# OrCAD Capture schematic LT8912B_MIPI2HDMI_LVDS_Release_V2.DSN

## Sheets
1 03.Revision History: company: Seabery Soluciones S.L.
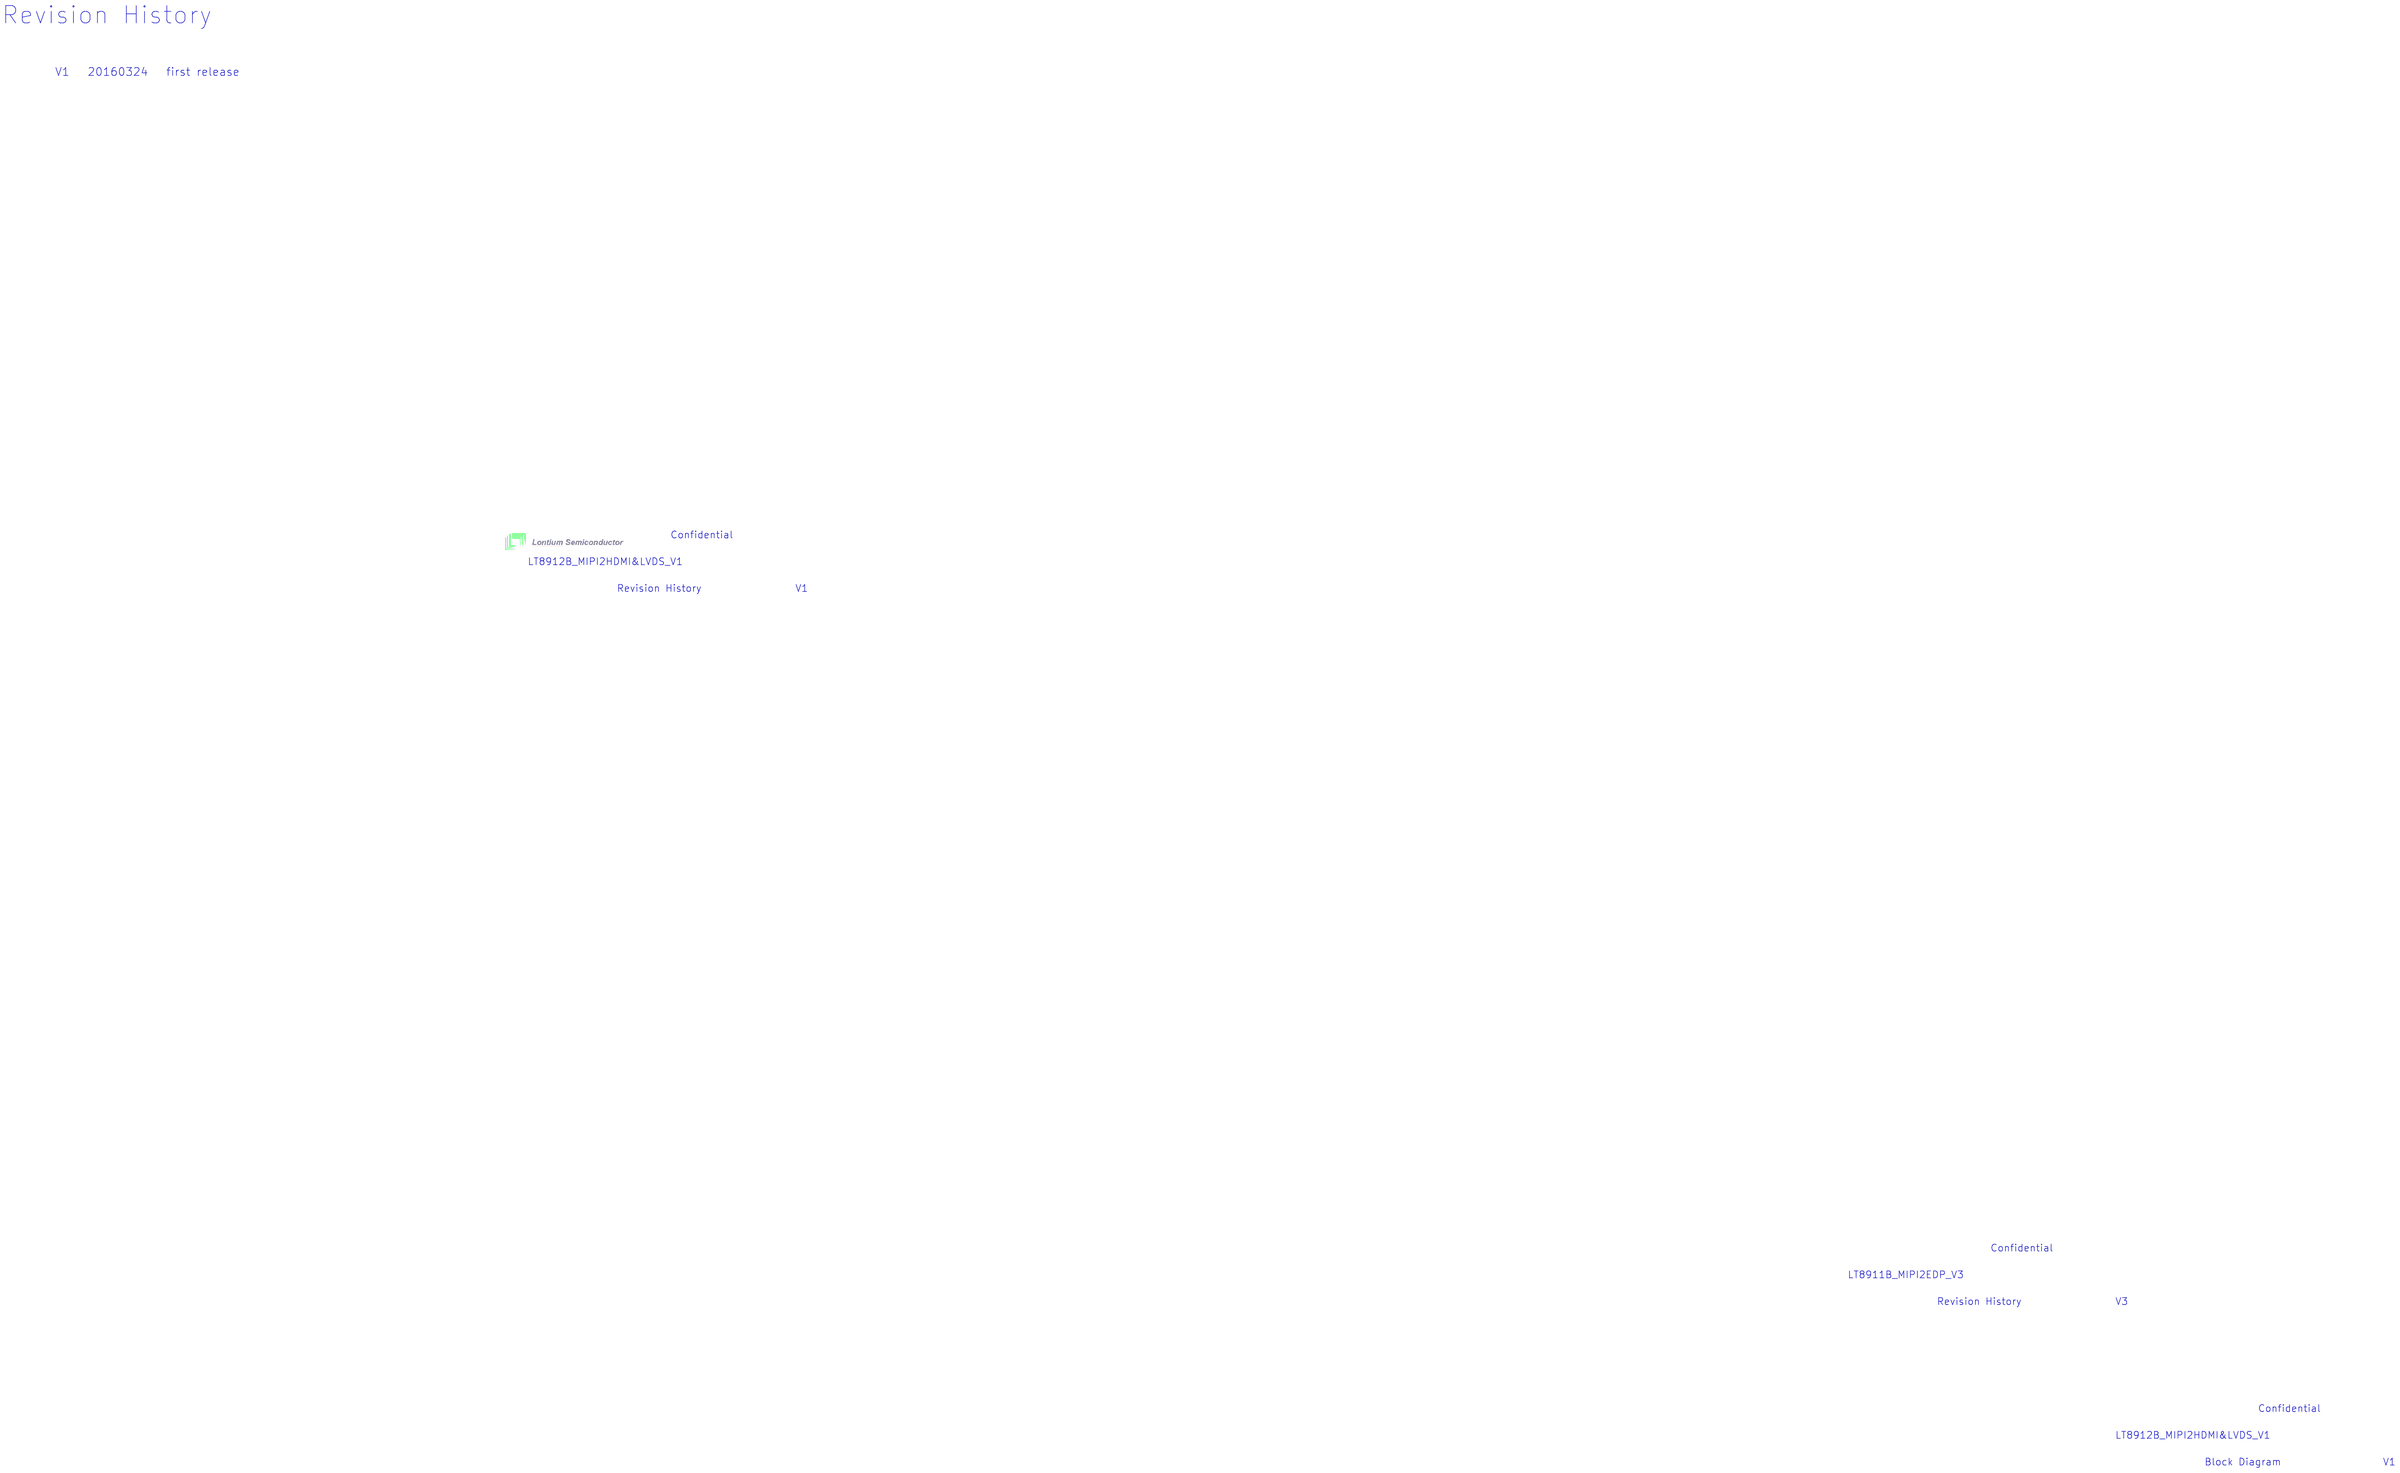
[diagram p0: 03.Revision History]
2 01.Block Diagram
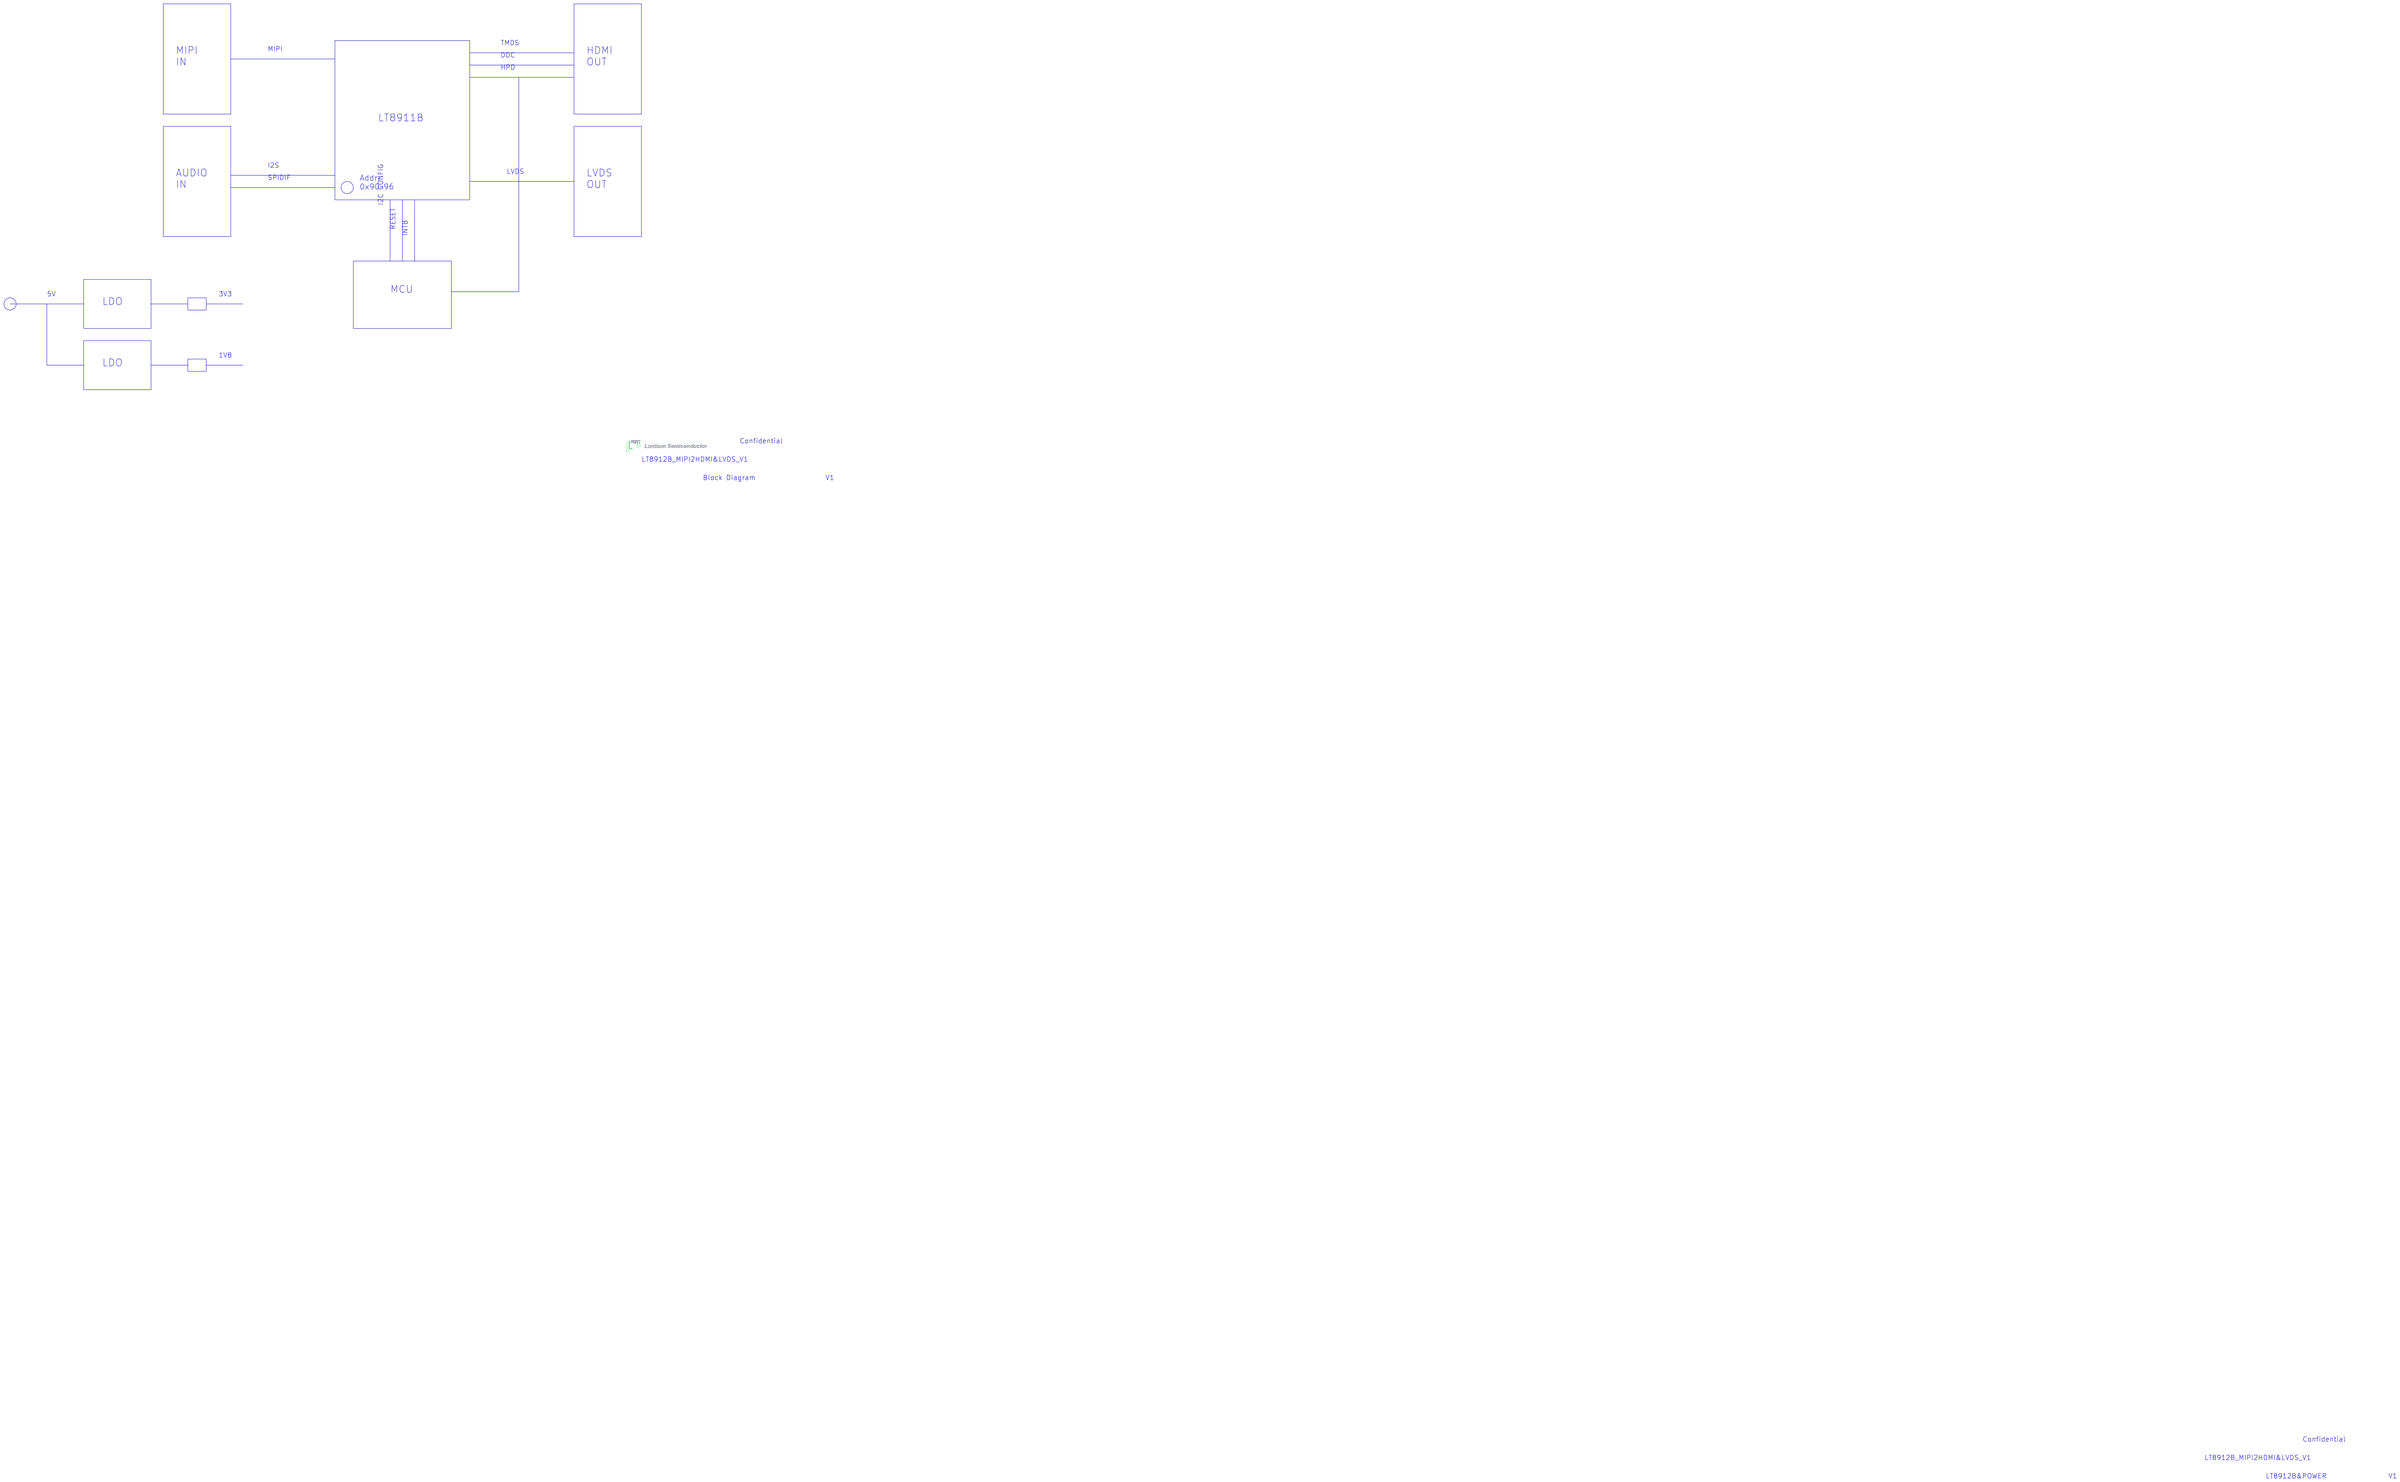
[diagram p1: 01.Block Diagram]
3 02.LT8912B&MCU: size A2
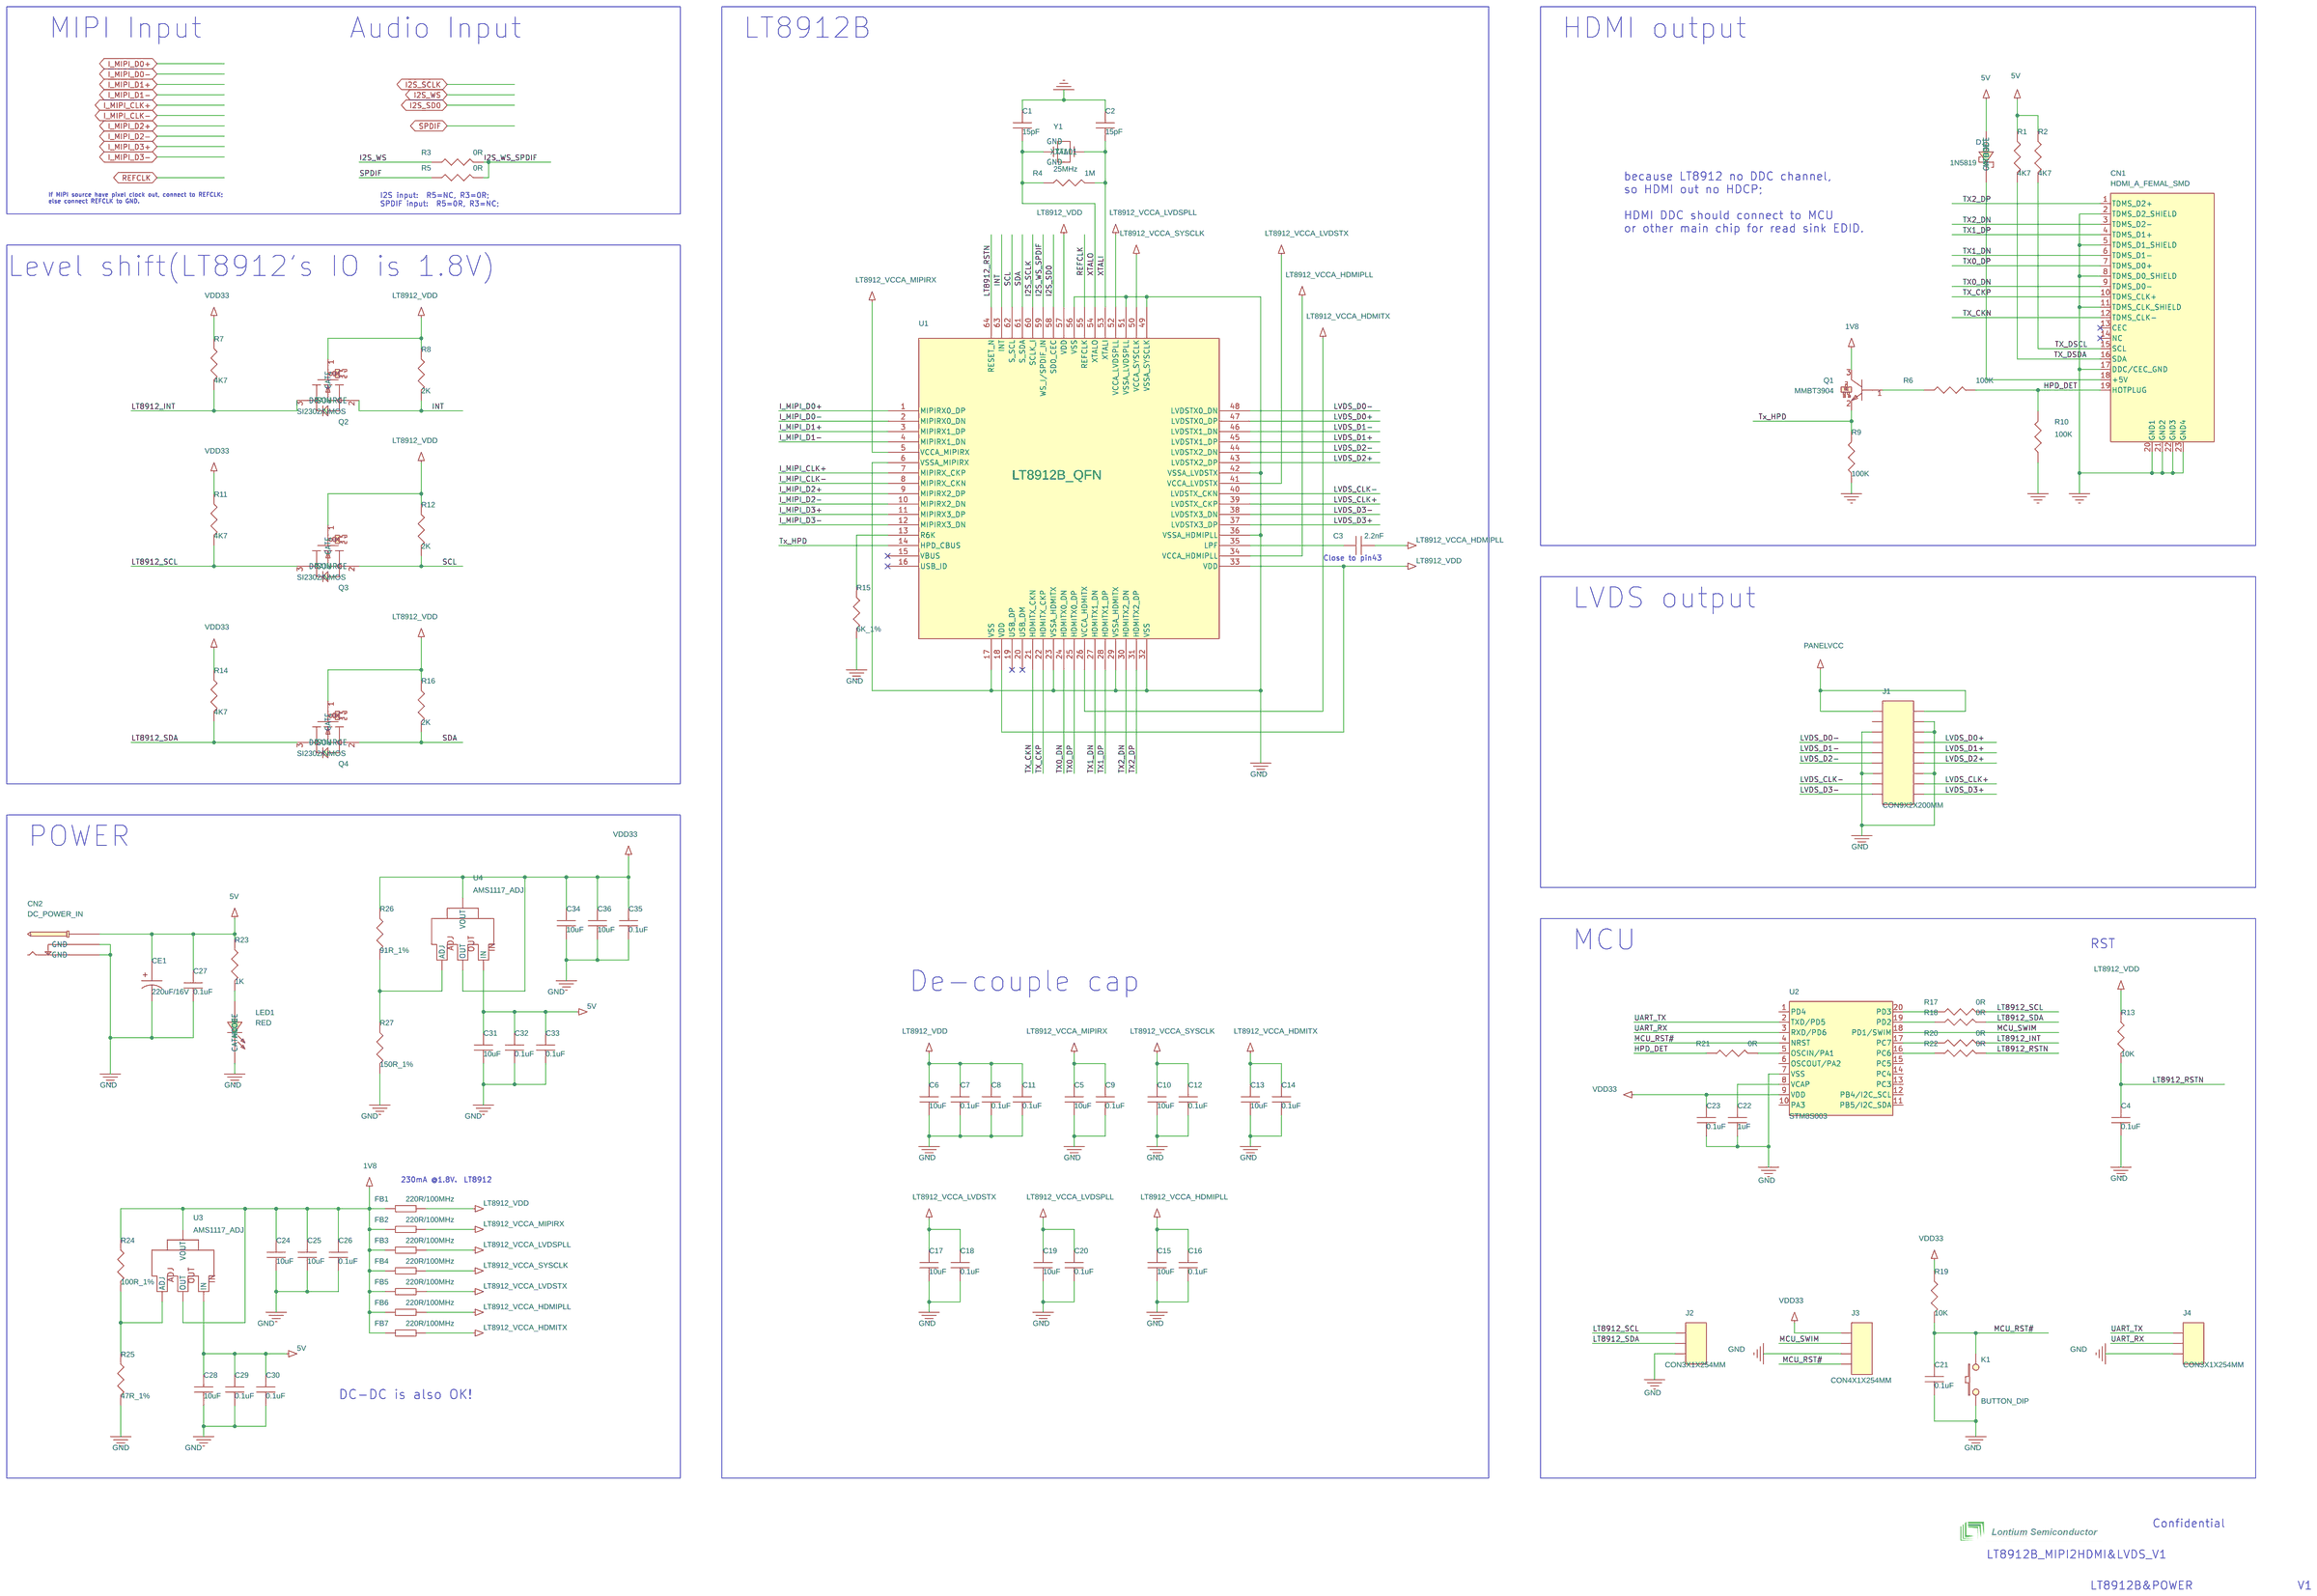
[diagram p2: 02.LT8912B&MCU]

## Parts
C1  15pF  [0603-C]
C2  15pF  [0603-C]
C3  2.2nF  [0603-C]
C4  0.1uF  [0603-C]
C5  10uF  [0603-C]
C6  10uF  [0603-C]
C7  0.1uF  [0603-C]
C8  0.1uF  [0603-C]
C9  0.1uF  [0603-C]
C10  10uF  [0603-C]
C11  0.1uF  [0603-C]
C12  0.1uF  [0603-C]
C13  10uF  [0603-C]
C14  0.1uF  [0603-C]
C15  10uF  [0603-C]
C16  0.1uF  [0402-C]
C17  10uF  [0603-C]
C18  0.1uF  [0603-C]
C19  10uF  [0603-C]
C20  0.1uF  [0603-C]
C21  0.1uF  [0603-C]
C22  1uF  [0603-C]
C23  0.1uF  [0603-C]
C24  10uF  [0603-C]
C25  10uF  [0603-C]
C26  0.1uF  [0603-C]
C27  0.1uF  [0603-C]
C28  10uF  [0603-C]
C29  0.1uF  [0603-C]
C30  0.1uF  [0603-C]
C31  10uF  [0603-C]
C32  0.1uF  [0603-C]
C33  0.1uF  [0603-C]
C34  10uF  [0603-C]
C35  0.1uF  [0603-C]
C36  10uF  [0603-C]
CE1  220uF/16V  [CD7_3MM]
CN1  HDMI_A_FEMAL_SMD  [HDMI_TYPEA_FEMAL_SMD]
CN2  DC_POWER_IN  [DC005]
D1  1N5819  [1N5819_1206]
FB1  220R/100MHz  [0603-FB]
FB2  220R/100MHz  [0603-FB]
FB3  220R/100MHz  [0603-FB]
FB4  220R/100MHz  [0603-FB]
FB5  220R/100MHz  [0603-FB]
FB6  220R/100MHz  [0603-FB]
FB7  220R/100MHz  [0603-FB]
J1  CON9X2X200MM  [CON9X2X200MM]
J2  CON3X1X254MM  [CON3X1X254MM]
J3  CON4X1X254MM  [CON4X1X254MM]
J4  CON3X1X254MM  [CON3X1X254MM]
K1  BUTTON_DIP  [BUTTON_DIP]
LED1  RED  [0603-LED]
Q1  MMBT3904  [MMBT3904_SOT23]
Q2  SI2302/NMOS  [SI2302_SOT23]
Q3  SI2302/NMOS  [SI2302_SOT23]
Q4  SI2302/NMOS  [SI2302_SOT23]
R1  4K7  [0603-R]
R2  4K7  [0603-R]
R3  0R  [0603-R]
R4  1M  [0603-R]
R5  0R  [0603-R]
R6  100K  [0603-R]
R7  4K7  [0603-R]
R8  2K  [0603-R]
R9  100K  [0603-R]
R10  100K  [0603-R]
R11  4K7  [0603-R]
R12  2K  [0603-R]
R13  10K  [0603-R]
R14  4K7  [0603-R]
R15  6K_1%  [0603-R]
R16  2K  [0603-R]
R17  0R  [0603-R]
R18  0R  [0603-R]
R19  10K  [0603-R]
R20  0R  [0603-R]
R21  0R  [0603-R]
R22  0R  [0603-R]
R23  1K  [0603-R]
R24  100R_1%  [0603-R]
R25  47R_1%  [0603-R]
R26  91R_1%  [0603-R]
R27  150R_1%  [0603-R]
U1  LT8912B_QFN  [LT8912B_QFN64_EPAD]
U2  STM8S003  [STM8S103_TSSOP20]
U3  AMS1117_ADJ  [AMS1117_ADJ_SOT-223_4]
U4  AMS1117_ADJ  [AMS1117_ADJ_SOT-223_4]
Y1  25MHz  [CRY_3225]

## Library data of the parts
C1 C2 = CAP_NP0603: PCB Footprint Status: Checked; Part Number: 117-00-3002; Part Status: On Hand; Part Type: CAPACITOR; Price: 0.0072; Purchase Information: 13510796878 伊美尔电子; Standard PCB Footprint: 0603
C3 = CAP_NP0603: PCB Footprint Status: Checked; Part Number: 117-00-3023; Part Status: On Hand; Part Type: CAPACITOR; Price: 0.0072; Purchase Information: 13510796878 伊美尔电子; Standard PCB Footprint: 0603
C4 C7-C9 C11 C12 C14 C16 C18 C20 C21 C23 C26 C27 C29 C30 C32 C33 C35 = CAP_NP0603: PCB Footprint Status: Checked; Part Number: 117-00-3036; Part Status: On Hand; Part Type: CAPACITOR; Price: 0.0072; Purchase Information: 13510796878 伊美尔电子; Standard PCB Footprint: 0603
C5 C6 C10 C13 C15 C17 C19 C24 C25 C28 C31 C34 C36 = CAP_NP0603: PCB Footprint Status: Checked; Part Number: 117-00-3043; Part Status: On Hand; Part Type: CAPACITOR; Price: 0.1; Purchase Information: 13510796878 伊美尔电子; Standard PCB Footprint: 0603
C22 = CAP_NP0603: PCB Footprint Status: Checked; Part Number: 117-00-3040; Part Status: On Hand; Part Type: CAPACITOR; Price: 0.0072; Purchase Information: 13510796878 伊美尔电子; Standard PCB Footprint: 0603
CE1 = ECAP_POL: Part Number: 117-00-3057; Part Status: On Hand; Part Type: ELECTROLYSIS CAPACITOR; Price: 0.0738; Purchase Information: 15914148925 腾光达电子
CN1 = HDMI_TYPEA: Part Number: 226-00-3080; Part Status: On Hand; Part Type: HDMI; Price: 1; Purchase Information: 13811699081 国际世联
CN2 = DC005: Part Description: DC JACK,DC005; Part Number: 226-00-3088; Part Status: On Hand; Part Type: JACK; Price: 0.2; Purchase Information: 18969723602 乐清市鑫皖电子
D1 = SM340A: Data Sheet: 1N5819.pdf; PCB Footprint Status: Checked; Part Description: 1N5819, 1206; Part Number: 647-00-3059; Part Status: Not On Hand; Part Type: DIODE; Price: 0.065; Purchase Information: 13632959229 深圳伟达电子 张小姐; Standard PCB Footprint: 1206
FB1-FB7 = BEAD0603: PCB Footprint Status: Checked; Part Number: 647-01-3069; Part Status: On Hand; Part Type: BEAD; Price: 0.011; Purchase Information: 07558255526 小商行电子; Standard PCB Footprint: 0603
J1 = CON9X2X200MM: PCB Footprint Status: Checked; Part Number: 226-00-3068; Part Status: On Hand; Part Type: CONNECTOR; Price: 0; Purchase Information: 13714111152 福强电子科技 朱先生; Standard PCB Footprint: 9*2*2.00MM
J2 = CON3X1X254MM: PCB Footprint Status: Checked; Part Number: 226-00-3002; Part Status: On Hand; Part Type: CONNECTOR; Price: 0; Purchase Information: 13714111152 福强电子科技 朱先生; Standard PCB Footprint: 3*1*2.54MM
J3 = CON4X1X254MM: PCB Footprint Status: Checked; Part Number: 226-00-3003; Part Status: On Hand; Part Type: CONNECTOR; Price: 0; Purchase Information: 13714111152 福强电子科技 朱先生; Standard PCB Footprint: 4*1*2.54MM
J4 = CON3X1X254MM: Part Number: 226-00-3002
K1 = BUTTON: PCB Footprint Status: Checked; Part Number: 647-00-3033; Part Status: On Hand; Price: 0.1; Purchase Information: 15996744099 江苏泗阳九九电子
LED1 = LED0603: PCB Footprint Status: Checked; Part Description: red; Part Number: 647-00-3064; Part Status: On Hand; Part Type: LED; Price: 0.04; Purchase Information: 021-53081803 上海荣达威电子
Q1 = MMBT3904: Data Sheet: 2N3904.pdf; PCB Footprint Status: Checked; Part Number: 647-01-3048; Part Status: Not On Hand; Part Type: NPN; Price: 0.06; Purchase Information: 15914148925 腾光达电子; Standard PCB Footprint: SOT23
Q2-Q4 = SI2302: Data Sheet: SI2302.pdf; Manufacturer: Vishay Siliconix; Manufacturer Part Number: Si2302ADS-T1; PCB Footprint Status: Checked; Part Number: 647-00-3013; Part Status: On Hand; Part Type: NMOS; Price: 0.085; Purchase Information: 13632966678 睿博电子科技; Standard PCB Footprint: SOT23
R1 R2 R7 R11 R12 R14 R16 = RES0603: PCB Footprint Status: Checked; Part Number: 737-00-3042; Part Status: On Hand; Part Type: RESISTOR; Price: 0.0028; Purchase Information: 13510796878 伊美尔电子; Standard PCB Footprint: 0603; Tolerance: %5
R3 R5 R21 = RES0603: PCB Footprint Status: Checked; Part Number: 737-00-3110; Part Status: On Hand; Part Type: RESISTOR; Price: 0.0028; Purchase Information: 13510796878 伊美尔电子; Standard PCB Footprint: 0603; Tolerance: %5
R4 = RES0603: PCB Footprint Status: Checked; Part Number: 737-00-3074; Part Status: On Hand; Part Type: RESISTOR; Price: 0.0028; Purchase Information: 13510796878 伊美尔电子; Standard PCB Footprint: 0603; Tolerance: %5
R6 R9 R10 = RES0603: PCB Footprint Status: Checked; Part Number: 737-00-3066; Part Status: On Hand; Part Type: RESISTOR; Price: 0.0028; Purchase Information: 13510796878 伊美尔电子; Standard PCB Footprint: 0603; Tolerance: %5
R8 = RES0603: PCB Footprint Status: Checked; Part Number: 737-00-3036; Part Status: On Hand; Part Type: RESISTOR; Price: 0.0028; Purchase Information: 13510796878 伊美尔电子; Standard PCB Footprint: 0603; Tolerance: %5
R13 R15 R19 = RES0603: PCB Footprint Status: Checked; Part Number: 737-00-3049; Part Status: On Hand; Part Type: RESISTOR; Price: 0.0028; Purchase Information: 13510796878 伊美尔电子; Standard PCB Footprint: 0603; Tolerance: %5
R17 R18 R20 R22 = RES0603: PCB Footprint Status: Checked; Part Number: 737-00-3000; Part Status: On Hand; Part Type: RESISTOR; Price: 0; Purchase Information: 13510796878 伊美尔电子; Standard PCB Footprint: 0603; Tolerance: %5
R23 = RES0603: PCB Footprint Status: Checked; Part Number: 737-00-3032; Part Status: On Hand; Part Type: RESISTOR; Price: 0.0028; Purchase Information: 13510796878 伊美尔电子; Standard PCB Footprint: 0603; Tolerance: %5
R24 = RES0603: PCB Footprint Status: Checked; Part Number: 737-00-3017; Part Status: On Hand; Part Type: RESISTOR; Price: 0.0028; Purchase Information: 13510796878 伊美尔电子; Standard PCB Footprint: 0603; Tolerance: %5
R25 = RES0603: PCB Footprint Status: Checked; Part Number: 737-00-3012; Part Status: On Hand; Part Type: RESISTOR; Price: 0.0028; Purchase Information: 13510796878 伊美尔电子; Standard PCB Footprint: 0603; Tolerance: %5
R26 = RES0603: PCB Footprint Status: Checked; Part Number: 737-00-3016; Part Status: On Hand; Part Type: RESISTOR; Price: 0.0028; Purchase Information: 13510796878 伊美尔电子; Standard PCB Footprint: 0603; Tolerance: %5
R27 = RES0603: PCB Footprint Status: Checked; Part Number: 737-00-3019; Part Status: On Hand; Part Type: RESISTOR; Price: 0.0028; Purchase Information: 13510796878 伊美尔电子; Standard PCB Footprint: 0603; Tolerance: %5
U1 = LT8912B_QFN64_0: Part Description: LT8912B,QFN64; Part Number: 566-00-3037; Part Status: On Hand; Part Type: LontiumIC; Standard PCB Footprint: QFN64
U2 = STM8S103_TSSOP20: Data Sheet: STM8S103.pdf; PCB Footprint Status: Checked; Part Number: 628-00-3001; Part Status: On Hand; Part Type: MCU; Price: 0; Standard PCB Footprint: TSSOP20
U3 U4 = AMS1117_ADJ: Data Sheet: AMS1117_ADJ.pdf; Part Description: AMS1117-ADJ; Part Number: 427-00-3008; Part Status: On Hand; Part Type: REGULATOR; Price: 0.3; Purchase Information: 0755-83229575陈; Standard PCB Footprint: SOT-223
Y1 = CRYSTAL_4PIN: Data Sheet: CRYSTAL_4PIN.pdf; PCB Footprint Status: Checked; Part Description: 4 pin, passive; Part Number: 647-00-3038; Part Status: On Hand; Part Type: CRYSTAL; Price: 1; Purchase Information: 0755-83609566 华瑞纳电子; Standard PCB Footprint: LLC

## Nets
1V8: C24.1 C25.1 C26.1 FB1.1 FB2.1 FB3.1 FB4.1 FB5.1 FB6.1 FB7.1 Q1.C R24.1 U3.2(OUT) U3.4(VOUT)
5V: C27.1 C28.1 C29.1 C30.1 C31.1 C32.1 C33.1 CE1.1 CN2.2 D1.A(ANODE) R1.1 R2.1 R23.1 U3.3(IN) U4.3(IN)
GND: C1.1 C2.1 C4.2 C5.2 C6.2 C7.2 C8.2 C9.2 C10.2 C11.2 C12.2 C13.2 C14.2 C15.2 C16.2 C17.2 C18.2 C19.2 C20.2 C21.2 C22.2 C23.2 C24.2 C25.2 C26.2 C27.2 C28.2 C29.2 C30.2 C31.2 C32.2 C33.2 C34.2 C35.2 C36.2 CE1.2 CN1.2(TDMS_D2_SHIELD) CN1.5(TDMS_D1_SHIELD) CN1.8(TDMS_D0_SHIELD) CN1.11(TDMS_CLK_SHIELD) CN1.17(DDC/CEC_GND) CN1.20(GND1) CN1.21(GND2) CN1.22(GND3) CN1.23(GND4) CN2.1(GND) CN2.3(GND) J1.4 J1.5 J1.6 J1.13 J1.14 J2.3 J3.3 J4.3 K1.1 LED1.C(CATHODE) R9.1 R10.1 R15.2 R25.2 R27.2 U1.6(VSSA_MIPIRX) U1.17(VSS) U1.23(VSSA_HDMITX) U1.29(VSSA_HDMITX) U1.32(VSS) U1.36(VSSA_HDMIPLL) U1.42(VSSA_LVDSTX) U1.49(VSSA_SYSCLK) U1.51(VSSA_LVDSPLL) U1.56(VSS) U2.7(VSS) Y1.2(GND) Y1.4(GND)
VDD33: C23.1 C34.1 C35.1 C36.1 J3.1 R7.1 R11.1 R14.1 R19.1 R26.1 U2.9(VDD) U4.2(OUT) U4.4(VOUT)
HPD_DET: CN1.19(HOTPLUG) R6.2 R10.2 R21.1
I2S_SCLK: U1.60(SCLK_I)
I2S_SD0: U1.58(SD0_CEC)
I2S_WS: R3.1
I2S_WS_SPDIF: R3.2 R5.2 U1.59(WS_I/SPDIF_IN)
I_MIPI_CLK+: U1.7(MIPIRX_CKP)
I_MIPI_CLK-: U1.8(MIPIRX_CKN)
I_MIPI_D0+: U1.1(MIPIRX0_DP)
I_MIPI_D0-: U1.2(MIPIRX0_DN)
I_MIPI_D1+: U1.3(MIPIRX1_DP)
I_MIPI_D1-: U1.4(MIPIRX1_DN)
I_MIPI_D2+: U1.9(MIPIRX2_DP)
I_MIPI_D2-: U1.10(MIPIRX2_DN)
I_MIPI_D3+: U1.11(MIPIRX3_DP)
I_MIPI_D3-: U1.12(MIPIRX3_DN)
INT: Q2.S(SOURCE) R8.2 U1.63(INT)
LT8912_INT: Q2.D(DRAIN) R7.2 R20.2
LT8912_RSTN: C4.1 R13.2 R22.2 U1.64(RESET_N)
LT8912_SCL: J2.1 Q3.D(DRAIN) R11.2 R17.2
LT8912_SDA: J2.2 Q4.D(DRAIN) R14.2 R18.2
LT8912_VCCA_HDMIPLL: C3.2 C15.1 C16.1 FB6.2 U1.34(VCCA_HDMIPLL)
LT8912_VCCA_HDMITX: C13.1 C14.1 FB7.2 U1.26(VCCA_HDMITX)
LT8912_VCCA_LVDSPLL: C19.1 C20.1 FB3.2 U1.52(VCCA_LVDSPLL)
LT8912_VCCA_LVDSTX: C17.1 C18.1 FB5.2 U1.41(VCCA_LVDSTX)
LT8912_VCCA_MIPIRX: C5.1 C9.1 FB2.2 U1.5(VCCA_MIPIRX)
LT8912_VCCA_SYSCLK: C10.1 C12.1 FB4.2 U1.50(VCCA_SYSCLK)
LT8912_VDD: C6.1 C7.1 C8.1 C11.1 FB1.2 Q2.G(GATE) Q3.G(GATE) Q4.G(GATE) R8.1 R12.1 R13.1 R16.1 U1.18(VDD) U1.33(VDD) U1.57(VDD)
LVDS_CLK+: J1.16 U1.39(LVDSTX_CKP)
LVDS_CLK-: J1.15 U1.40(LVDSTX_CKN)
LVDS_D0+: J1.8 U1.47(LVDSTX0_DP)
LVDS_D0-: J1.7 U1.48(LVDSTX0_DN)
LVDS_D1+: J1.10 U1.45(LVDSTX1_DP)
LVDS_D1-: J1.9 U1.46(LVDSTX1_DN)
LVDS_D2+: J1.12 U1.43(LVDSTX2_DP)
LVDS_D2-: J1.11 U1.44(LVDSTX2_DN)
LVDS_D3+: J1.18 U1.37(LVDSTX3_DP)
LVDS_D3-: J1.17 U1.38(LVDSTX3_DN)
MCU_RST#: C21.1 J3.4 K1.2 R19.2 U2.4(NRST)
MCU_SWIM: J3.2 U2.18(PD1/SWIM)
PANELVCC: J1.1 J1.2
REFCLK: U1.55(REFCLK)
SCL: Q3.S(SOURCE) R12.2 U1.62(S_SCL)
SDA: Q4.S(SOURCE) R16.2 U1.61(S_SDA)
SPDIF: R5.1
TX0_DN: CN1.9(TDMS_D0-) U1.24(HDMITX0_DN)
TX0_DP: CN1.7(TDMS_D0+) U1.25(HDMITX0_DP)
TX1_DN: CN1.6(TDMS_D1-) U1.27(HDMITX1_DN)
TX1_DP: CN1.4(TDMS_D1+) U1.28(HDMITX1_DP)
TX2_DN: CN1.3(TDMS_D2-) U1.30(HDMITX2_DN)
TX2_DP: CN1.1(TDMS_D2+) U1.31(HDMITX2_DP)
TX_CKN: CN1.12(TDMS_CLK-) U1.21(HDMITX_CKN)
TX_CKP: CN1.10(TDMS_CLK+) U1.22(HDMITX_CKP)
TX_DSCL: CN1.15(SCL) R2.2
TX_DSDA: CN1.16(SDA) R1.2
Tx_HPD: Q1.E R9.2 U1.14(HPD_CBUS)
UART_RX: J4.2 U2.3(RXD/PD6)
UART_TX: J4.1 U2.2(TXD/PD5)
XTALI: C2.2 R4.2 U1.53(XTALI) Y1.1(XTAL0)
XTALO: C1.2 R4.1 U1.54(XTALO) Y1.3(XTAL1)
N204821: Q1.B R6.1
N256577: CN1.18(+5V) D1.C(CATHODE)
N697177: C3.1 U1.35(LPF)
N698668: R15.1 U1.13(R6K)
N790496: R21.2 U2.5(OSCIN/PA1)
N790500: R22.1 U2.16(PC6)
N790550: C22.1 U2.8(VCAP)
N790596: R20.1 U2.17(PC7)
N790798: R17.1 U2.20(PD3)
N790814: R18.1 U2.19(PD2)
N796787: R24.2 R25.1 U3.1(ADJ)
N805106: R26.2 R27.1 U4.1(ADJ)
N815196: LED1.A(ANODE) R23.2

Not connected (* = marked no-connect by the designer): CN1 13(CEC)* 14(NC)*; J1 3; U1 15(VBUS)* 16(USB_ID)* 19(USB_DP)* 20(USB_DM)*; U2 1(PD4) 6(OSCOUT/PA2) 10(PA3) 11(PB5/I2C_SDA) 12(PB4/I2C_SCL) 13(PC3) 14(PC4) 15(PC5)

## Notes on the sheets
sheet 1
- Revision History
- V1   20160324   first release
- Confidential
- LT8912B_MIPI2HDMI&LVDS_V1
- Revision History
- V1
- Confidential
- LT8911B_MIPI2EDP_V3
- Revision History
- V3
- Confidential
- LT8912B_MIPI2HDMI&LVDS_V1
- Block Diagram
- V1
sheet 2
- TMDS
- MIPI
  IN
- MIPI
- DDC
- HDMI
  OUT
- HPD
- LT8911B
- I2S
- AUDIO
  IN
- SPIDIF
- Addr:
  0x90~96
- LVDS
- LVDS
  OUT
- I2C CONFIG
- RESET
- INTB
- 5V
- 3V3
- MCU
- LDO
- 1V8
- LDO
- Confidential
- LT8912B_MIPI2HDMI&LVDS_V1
- Block Diagram
- V1
- Confidential
- LT8912B_MIPI2HDMI&LVDS_V1
- LT8912B&POWER
- V1
sheet 3
- MIPI Input
- Audio Input
- LT8912B
- HDMI output
- because LT8912 no DDC channel,
  so HDMI out no HDCP;
  HDMI DDC should connect to MCU
  or other main chip for read sink EDID.
- If MIPI source have pixel clock out, connect to REFCLK;
  else connect REFCLK to GND.
- I2S input:  R5=NC, R3=0R;
  SPDIF input:  R5=0R, R3=NC;
- Level shift(LT8912's IO is 1.8V)
- Close to pin43
- LVDS output
- POWER
- MCU
- RST
- De-couple cap
- 230mA @1.8V， LT8912
- DC-DC is also OK!
- Confidential
- LT8912B_MIPI2HDMI&LVDS_V1
- LT8912B&POWER
- V1
